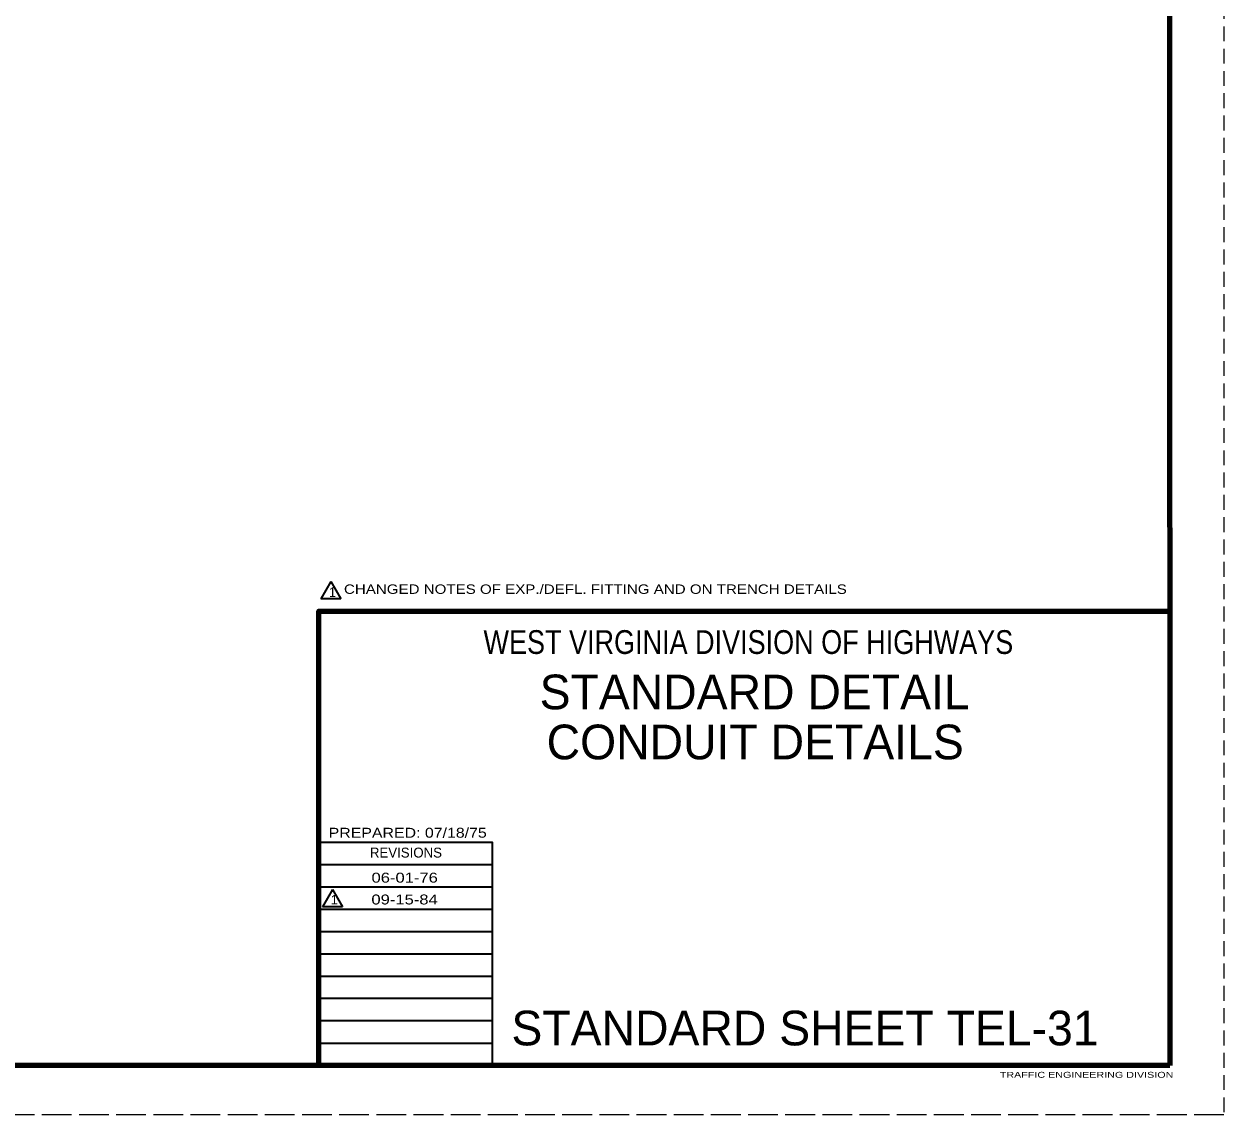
# Model space of a CAD drawing. Extents: x -1 to 679, y 0 to 440.
# Drawn here: x 436.5 to 678.6, y -0.3 to 219.8 of the extents above; entities that cross this region are included whole.
import ezdxf
from ezdxf.enums import TextEntityAlignment as Align

# ---------------------------------------------------------------- set-up
doc = ezdxf.new("R2010")
doc.units = 0
doc.linetypes.add('LONG_DASHED', pattern=[7.5, 6, -1.5])
doc.linetypes.add('MEDIUM_DASHED', pattern=[4.5, 3, -1.5])
doc.layers.add('1', color=7, linetype='Continuous', lineweight=35)
doc.layers.add('61', color=7, linetype='Continuous', lineweight=35)

msp = doc.modelspace()

# ---------------------------------------------------------------- linework, layer by layer
at = {"layer": '1', "linetype": 'MEDIUM_DASHED', "lineweight": 13}
msp.add_line((678.644, 439.785), (678.624, -0.235), dxfattribs=at)
at = {"layer": '1'}
for p, q in [((498.417, 107.314), (496.417, 103.85)), ((498.417, 107.314), (500.417, 103.85)), ((500.417, 103.85), (496.417, 103.85)), ((531.024, 50.185), (496.044, 50.185)), ((531.024, 45.685), (496.044, 45.685)), ((498.774, 45.204), (496.774, 41.74)), ((498.774, 45.204), (500.774, 41.74)), ((531.024, 41.185), (496.044, 41.185)), ((500.774, 41.74), (496.774, 41.74)), ((531.024, 36.665), (496.044, 36.665)), ((531.024, 32.185), (496.044, 32.185)), ((531.024, 27.705), (496.044, 27.705)), ((531.024, 23.205), (496.044, 23.205)), ((531.024, 18.705), (496.044, 18.705)), ((531.024, 14.185), (496.044, 14.185))]:
    msp.add_line(p, q, dxfattribs=at)
at = {"layer": '1', "lineweight": 158}
msp.add_lwpolyline([(496.024, 9.745), (496.024, 101.325), (667.684, 101.325)], dxfattribs=at)
at = {"layer": '1'}
msp.add_lwpolyline([(531.024, 9.705), (531.024, 54.665), (496.044, 54.665)], dxfattribs=at)
at = {"layer": '61', "lineweight": 158}
for p, q in [((667.664, 429.785), (667.684, 9.745)), ((667.684, 9.745), (28.624, 9.765))]:
    msp.add_line(p, q, dxfattribs=at)
at = {"layer": '61', "linetype": 'LONG_DASHED', "lineweight": 13}
msp.add_line((678.624, -0.235), (-1.436, -0.255), dxfattribs=at)

# ---------------------------------------------------------------- texts
at = {"layer": '1'}
for s, height, width, p in [('CHANGED NOTES OF EXP./DEFL. FITTING AND ON TRENCH DETAILS', 1.9, 1.2, (501.071, 104.842)), ('PREPARED: 07/18/75', 1.998, 1.2, (497.984, 55.665)), ('TRAFFIC ENGINEERING DIVISION', 1.2, 1.35, (633.404, 7.245))]:
    msp.add_text(s, height=height, dxfattribs=dict(at, width=width)).set_placement(p)
for s, height, p in [('1', 1.9, (498.047, 104.237)), ('REVISIONS', 1.998, (506.304, 51.665)), ('1', 1.9, (498.419, 42.213)), ('STANDARD SHEET TEL-31', 6.993, (534.864, 13.785))]:
    msp.add_text(s, height=height, dxfattribs=at).set_placement(p)
for s, height, width, p in [('WEST VIRGINIA DIVISION OF HIGHWAYS', 4.795, 0.85, (582.672, 92.725)), ('06-01-76', 2, 1.25, (513.324, 46.605)), ('09-15-84', 2, 1.25, (513.304, 42.205))]:
    msp.add_text(s, height=height, dxfattribs=dict(at, width=width)).set_placement(p, align=Align.CENTER)
for s, p in [('STANDARD DETAIL', (583.941, 81.565)), ('CONDUIT DETAILS', (584.051, 71.477))]:
    msp.add_text(s, height=6.993, dxfattribs=at).set_placement(p, align=Align.CENTER)

doc.saveas('drawing.dxf')
